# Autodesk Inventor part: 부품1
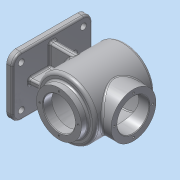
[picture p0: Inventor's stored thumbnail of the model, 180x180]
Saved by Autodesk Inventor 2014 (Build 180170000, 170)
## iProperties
Created: 2016-09
Part Number: 부품1
Material: 알루미늄 6061
Document SubType Name: Modeling
Designer: 402-003
Density: 2.71 g/cm^3
Appearance: 알루미늄 - 평지
Mass: 972.695 g
Surface Area: 1283.02 cm^2
Volume: 358.928 cm^3
Author: 402-003
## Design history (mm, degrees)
sketch "스케치1"
  geometry: L1 (-61, 0)-(61, 0); L2 (-61, 38)-(-49, 38); L3 (-49, 38)-(-49, 45); L4 (-44, 50)-(46.374, 50); L5 (46.374, 47)-(-44, 47); L6 (-46, 45)-(-46, 27); L7 (-61, 38)-(-61, 27); L8 (-61, 27)-(-46, 27); L9 (58, 0)-(61, 0); A1 r 115 centre (-54, 0) between (61, 0) and (50.937, 47.045); A2 r 112 centre (-54, 0) between (58, 0) and (48.199, 45.818); A3 r 2 centre (-44, 45) between (-44, 47) and (-46, 45); A4 r 5 centre (-44, 45) between (-44, 50) and (-49, 45); A5 r 5 centre (46.374, 45) between (50.937, 47.045) and (46.374, 50); A6 r 2 centre (46.374, 45) between (48.199, 45.818) and (46.374, 47); 5 further points
  constraints: 18 end point, 14 point on circle, 8 tangent, 6 centre point, 4 parallel, 4 point on line, 2 coincident, 2 equal radius, 2 midpoint, 2 perpendicular, 1 horizontal, 1 vertical alignment, 2 other
  dimensions: "d1" = 54 diameter of L8 L1; "d2" = 76 diameter of L2 L1; "d3" = 100 diameter of L4 L1; "d4" = 3 distance between parallel lines of L4 L5; "d5" = 115 radius of A1; "d6" = 110 distance from line of L9.end L3; "d7" = 12 distance of L2.start L2.end; "d8" = 2 radius of A3; "d9" = 5 radius of A4
revolve "회전1" sketch "스케치1" stored, may be unused: angle "d10" = 90 deg
node "작업 평면2"
sketch "스케치3"
  geometry: L1 (-61, -38)-(-61, 38) reference; C1 r 38 at (0, 0); 1 further point
  constraints: 1 centre point
  dimensions: "d12" = 76 diameter of C1; "d13" = 61 distance from line of C1.centre L1
extrude "돌출1" join sketch "스케치3" stored distance "d14" = 10; taper "d15" = 0 deg
hole "구멍1" diameter "d18" = 54; stored, may be unused: countersink angle "d22" = 90 deg, drill point angle "d24" = 118 deg; dims "d16" = 10, "d17" = 10, "d19" = 6, "d20" = 4, "d21" = 2, "d23" = 39
node "작업 평면3"
sketch "스케치4"
  geometry: L1 (-67.5, -50)-(67.5, -50); L2 (67.5, -50)-(67.5, 50); L3 (67.5, 50)-(-67.5, 50); L4 (-67.5, 50)-(-67.5, -50); L5 (-67.5, -50)-(67.5, 50); L6 (67.5, -50)-(-67.5, 50); L7 (-5, 40)-(5, 40); L8 (5, 40)-(5, -40); L9 (5, -40)-(-5, -40); L10 (-5, -40)-(-5, 40); L11 (-40, 5)-(40, 5); L12 (40, 5)-(40, -5); L13 (40, -5)-(-40, -5); L14 (-40, -5)-(-40, 5); C1 r 27 at (0, 0) reference; 1 further point
  constraints: 28 end point, 6 parallel, 3 horizontal, 3 perpendicular, 2 midpoint
  dimensions: "d26" = 135 distance of L2.end L3.end; "d27" = 100 distance of L3.end L1.start; "d28" = 10 distance of L11.end L12.end; "d29" = 10 distance of L7.start L7.end; "d30" = 5 distance from line of L10 C1.centre; "d31" = 5 distance from line of C1.centre L11; "d32" = 67.5 distance from line of C1.centre L2 (derived); "d33" = 80 distance of L9.end L7.start; "d34" = 80 distance of L11.start L11.end; "d35" = 40 distance from line of L14 C1.centre; "d36" = 40 distance from line of L7 C1.centre
extrude "돌출2" join sketch "스케치4" distance "d37" = 10; taper "d38" = 0 deg
extrude "돌출3" cut sketch "스케치4" stored distance "d39" = 10; taper "d40" = 0 deg
extrude "돌출4" join sketch "스케치4" stored distance "d41" = 10; taper "d42" = 0 deg
sketch "스케치5"
  geometry: L1 (38, -49)-(38, -61) reference; L2 (38, -61)-(27, -61) reference; L3 (27, -61)-(27, -46) reference; L4 (27, -46)-(45, -46) reference; L5 (47, -44)-(47, -27) reference; L6 (47, -27)-(65, -27) reference; L7 (65, -27)-(65, -38) reference; L8 (65, -38)-(50, -38) reference; L9 (50, -38)-(50, -44) reference; L10 (45, -49)-(38, -49) reference; L11 (50, 46.374)-(50, 38) reference; L12 (50, 38)-(65, 38) reference; L13 (65, 38)-(65, 27) reference; L14 (65, 27)-(47, 27) reference; L15 (47, 27)-(47, 46.374) reference; L16 (-47, 46.374)-(-47, -44) reference; L17 (-45, -46)-(-27, -46) reference; L18 (-27, -46)-(-27, -61) reference; L19 (-27, -61)-(-38, -61) reference; L20 (-38, -61)-(-38, -49) reference; L21 (-38, -49)-(-45, -49) reference; L22 (-50, -44)-(-50, -5) reference; L23 (-50, -5)-(-72, -5) reference; L24 (-72, -5)-(-72, -67.5) reference; L25 (-72, -67.5)-(-82, -67.5) reference; L26 (-82, -67.5)-(-82, 67.5) reference; L27 (-82, 67.5)-(-72, 67.5) reference; L28 (-72, 67.5)-(-72, 5) reference; L29 (-72, 5)-(-50, 5) reference; L30 (-50, 5)-(-50, 46.374) reference; L31 (-72, -40)-(-50, -38.075); L32 (-72, 40)-(-50, 38.075); A1 r 2 centre (45, -44) between (45, -46) and (47, -44) reference; A2 r 5 centre (45, -44) between (45, -49) and (50, -44) reference; A3 r 115 centre (0, -54) between (47.045, 50.937) and (-47.045, 50.937) reference; A4 r 5 centre (45, 46.374) between (50, 46.374) and (47.045, 50.937) reference; A5 r 2 centre (45, 46.374) between (47, 46.374) and (45.818, 48.199) reference; A6 r 112 centre (0, -54) between (45.818, 48.199) and (-45.818, 48.199) reference; A7 r 2 centre (-45, 46.374) between (-45.818, 48.199) and (-47, 46.374) reference; A8 r 2 centre (-45, -44) between (-47, -44) and (-45, -46) reference; A9 r 5 centre (-45, -44) between (-50, -44) and (-45, -49) reference; A10 r 5 centre (-45, 46.374) between (-47.045, 50.937) and (-50, 46.374) reference; 1 further point
  constraints: 4 end point, 4 point on line
  dimensions: "d43" = 40 vertical distance of point (0, 0) L31.start; "d44" = 95 deg angle of L31 L24; "d45" = 40 vertical distance of point (0, 0) L32.start; "d46" = 95 deg angle of L28 L32
  node "절단 모서리 투영1"
feature "리브1" dims "d47" = 1, "d48" = 10, "d49" = 0, "d50" = 0, "d51" = 1, "d52" = 1
feature "리브2" dims "d53" = 1, "d54" = 10, "d55" = 0, "d56" = 0, "d57" = 1, "d58" = 1
fillet "모깎기1" dims "d59" = 15
sketch "스케치6"
  geometry: C1 r 5 at (-35, 52.5); C2 r 5 at (35, 52.5); C3 r 5 at (35, -52.5); C4 r 5 at (-35, -52.5); A1 r 15 centre (35, 52.5) between (50, 52.5) and (35, 67.5) reference; A2 r 15 centre (-35, 52.5) between (-35, 67.5) and (-50, 52.5) reference; A3 r 15 centre (-35, -52.5) between (-50, -52.5) and (-35, -67.5) reference; A4 r 15 centre (35, -52.5) between (35, -67.5) and (50, -52.5) reference; 1 further point
  constraints: 4 centre point, 4 coincident
  dimensions: "d60" = 10 diameter of C1; "d61" = 10 diameter of C2; "d62" = 10 diameter of C3; "d63" = 10 diameter of C4
extrude "돌출5" cut sketch "스케치6" distance "d64" = 10; taper "d65" = 0 deg
sketch "스케치7" dims "d66" = 65
  geometry: C1 r 27 at (0, 0) reference; C2 r 38 at (0, 0) reference; 2 further points
  constraints: 2 vertical alignment, 1 coincident, 2 other
hole "구멍2" sketch "스케치7" at (0, 32.5) diameter "d67" = 3.242; stored, may be unused: countersink angle "d71" = 90 deg, drill point angle "d73" = 118 deg; dims "d68" = 8, "d69" = 4, "d70" = 2, "d72" = 10
sketch "스케치8" dims "d77" = 65
  geometry: C1 r 38 at (0, 0) reference; 3 further points
  constraints: 2 vertical alignment, 1 coincident, 2 other
hole "구멍3" sketch "스케치8" at (0, 32.5) diameter "d78" = 3.242; stored, may be unused: countersink angle "d82" = 90 deg, drill point angle "d84" = 118 deg; dims "d79" = 8, "d80" = 4, "d81" = 2, "d83" = 10
sketch "스케치9"
  geometry: C1 r 1.621 at (-32.5, 0) reference; C2 r 1.621 at (0, -32.5) reference; C3 r 1.621 at (32.5, 0) reference; C4 r 1.621 at (0, 32.5) reference; C5 r 27 at (0, 0) reference; C6 r 38 at (0, 0) reference; C7 r 32.5 at (0, 0)
  constraints: 1 centre point, 1 coincident
  dimensions: "d88" = 65 diameter of C7
node "작업 평면4"
sketch "스케치10"
  geometry: 2 further points
  constraints: 1 coincident, 1 other
feature "엠보싱1" sketch "스케치10" dims "d89" = 0.5, "d90" = 0
chamfer "모따기1" distance "d91" = 1; stored, may be unused: second distance "d92" = 2, angle "d93" = 45 deg
fillet "모깎기2" dims "d94" = 3
fillet "모깎기5" dims "d97" = 3
fillet "모깎기6" dims "d98" = 3
fillet "모깎기7" dims "d99" = 3
node "솔리드1"
pattern_circular "원형 패턴1" dims angle "d75" = 360 deg
pattern_circular "원형 패턴2" dims angle "d86" = 360 deg
other parameters: "d11" = 65, "d25" = -147
